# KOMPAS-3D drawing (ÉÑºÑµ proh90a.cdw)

Referenced files: Proh90a.cdw
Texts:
  ТМ-27А. КП.
  РЕЗЕЦ ПРОХОДНОЙ
  Текст на чертеже
  Размерные надписи
  Шероховатость
  Линия-выноска #1
  Линия-выноска #2
  Линия-выноска #3
  Отклонения формы и база
  Заголовок таблицы
  Ячейка таблицы
  Стрелка вида
  Обозначение изменения
  Фигурная скобка
  Номер узла
  Марка координационной оси
  VRCB
  Выносная надпись
  Обозначение узла
  Марка/позиционное обозначение с линией-выноской
  Марка/позиционное обозначение на линии
  Марка/позиционное обозначение без линии-выноски
  1.Обеспечить плотное прилегание режущей и
  опорной пластин в гнезде державки.
  2.Материал режущей пластины Т5К10
  ГОСТ 3882-74.
  3.Маркировать: материал режущей части резца,
  товарный знак завода изготовителя.
  4.Остальные технические требования по
  ГОСТ 19058-80.
  РЕЗЕЦ
  ПРОХОДНОЙ
  Павлий
  НТУ "ХПИ"
  каф. АиТ
  ТМ-27А. КП.-
Dimensions and other numbers on the sheet: 3; 7; 16; 1; 2; 4; 5; 50; 10; 40; 33; 125; 58; 0.8; 1:1; 0; 6; 8; 9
